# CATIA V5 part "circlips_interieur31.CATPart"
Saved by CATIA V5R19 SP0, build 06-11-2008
Part number: circlips_interieur
Publications: "Axe", "Appui_1", "Appui_2"
Material "Acier_120_1": density 7860 kg/m3, Young's modulus 2e+11 Pa, Poisson ratio 0.266, thermal expansion 1.17e-05 1/K
Bounding box of the stored display mesh (mm): x -32.383 to 32.383, y -32.031 to 32.5, z 0 to 2
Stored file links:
  U:\Rendu_cfao_elguidj\circlips_interieur31.CATPart
  C:\Users\Martin\Documents\IFMA\Cfao\Projet S3\Bibliothèque Catia\Circlips_int.txt
  D:\macros\Material_ltjj.CATMaterial
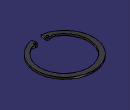
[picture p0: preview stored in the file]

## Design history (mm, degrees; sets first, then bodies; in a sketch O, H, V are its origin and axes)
Parameters
  `diametre-alesage` = 62 mm {design table}
  s_largeur = 2 mm {design table}
  a = 7.3 mm {design table}
  b = 5.5 mm {design table}
  Diam_trou = 2.5 mm {design table}
  D_gorge = 65 mm {design table}
  largeur_gorge = 2.15 mm {design table}
  reserve = 4.5 mm {design table}
  Resistance_gorge = 49800 (force) {design table}
  `Capacité_charge` = 60000 (force) {design table}
  arrondi_type_g = 2 mm {design table}
  `Capacité_charge_arrondi_g` = 13000 (force) {design table}
  PartNumber = "anneau élast. ext. d 62" {design table}
  designation = "anneau élast. ext. d 62" {= PartNumber}
Body1 (main body), material "Acier_120_1"
  Sketch1 on xy-plane, origin (0, 0, 0), H (1, 0, 0), V (0, 1, 0)
    arc A1 centre (0, 0) radius 32.5 from (5.5, -32.0312) to (0, 32.5) ccw
    arc A2 centre (0, -0.625) radius 27.625 from (13.4895, -24.7325) to (0, 27) ccw
    point P1 (0, -0.625)
    line L1 (5.5, -32.0312) -> (4.6686, -27.1891)
    point P2 (4.6686, -27.1891)
    arc A3 centre (7.1325, -26.766) radius 2.5 from (8.4377, -24.6337) to (4.6686, -27.1891) ccw
    circle A4 centre (7.1325, -26.766) radius 1.25
    arc A5 centre (11.048, -20.3692) radius 5 from (13.4895, -24.7325) to (8.4377, -24.6337) cw
    point P4 (13.4895, -24.7325)
    point P5 (8.4377, -24.6337)
    point P7 (0, 27)
    point P8 (0, 32.5)
    point P9 (5.5, -32.0312)
    construction circle A6 centre (0, 0) radius 31
    point P11 (-8.4377, -24.6337)
    point P12 (-13.4895, -24.7325)
    arc A7 centre (-11.048, -20.3692) radius 5 from (-13.4895, -24.7325) to (-8.4377, -24.6337) ccw
    point P14 (-4.6686, -27.1891)
    arc A8 centre (-7.1325, -26.766) radius 2.5 from (-8.4377, -24.6337) to (-4.6686, -27.1891) cw
    point P16 (-5.5, -32.0312)
    line L2 (-5.5, -32.0312) -> (-4.6686, -27.1891)
    point P17 (0, 27)
    arc A9 centre (0, -0.625) radius 27.625 from (-13.4895, -24.7325) to (0, 27) cw
    point P19 (0, 32.5)
    arc A10 centre (0, 0) radius 32.5 from (-5.5, -32.0312) to (0, 32.5) cw
    circle A11 centre (-7.1325, -26.766) radius 1.25
    construction circle A12 centre (0, 0) radius 25.2
    point P21 (6.4888, -24.3503)
    radius A6 = 31 {= `diametre-alesage` /2}
    radius A1 = 32.5 {= D_gorge /2}
    distance A2 P8 = 5.5 {= b}
    radius A4 = 1.25 {= Diam_trou /2}
    radius A3 = 2.5 {= Sketch1.radius(A4) *2}
    distance P9 V = 5.5 {= b}
    radius A5 = 5 {= Sketch1.radius(A3) *2}
    distance A2 A6 = 2.75 {= b /2}
    radius A12 = 25.2 {= Sketch1.radius(A1) -a}
    coincidence: P1 V, L1 O, P7 V, P8 V, P7 P17, P8 P19, A12 P21, P21 A3
    tangency: A3 L1, A5 A2, A5 A3, A12 A3
    symmetry: A5 A7 V, A3 A8 V, L1 L2 V, A2 A9 V, A1 A10 V, P4 P12 V, P5 P11 V, P2 P14 V, P9 P16 V, P7 P17 V, P8 P19 V, A4 A11 V
  Pad1: profile Sketch1, direction (0, 0, 1), length 2 {= s_largeur}
Relations
  design table, configuration 52, drives `diametre-alesage`, s_largeur, a, b, Diam_trou, D_gorge, largeur_gorge, reserve, Resistance_gorge, `Capacité_charge`, arrondi_type_g, `Capacité_charge_arrondi_g`, PartNumber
